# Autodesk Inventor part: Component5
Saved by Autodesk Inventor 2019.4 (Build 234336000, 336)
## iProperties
Created: 2020-02
Part Number: Component5
Material: Generic
Document SubType Name: Modeling
Designer: Administrator
Density: 1 g/cm^3
Appearance: Default
Title: Component5
Author: Administrator
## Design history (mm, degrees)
feature "Body1"
feature "Body2"
body "Solid1"
body "Solid2"
